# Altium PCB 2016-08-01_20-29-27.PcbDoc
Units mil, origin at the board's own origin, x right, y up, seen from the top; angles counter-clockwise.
Board outline 2000 x 2400 mil, 4 copper layers (Top Layer, MidLayer1, MidLayer2, Bottom Layer); 12 components, 6 nets, 24 pads, 32 vias.
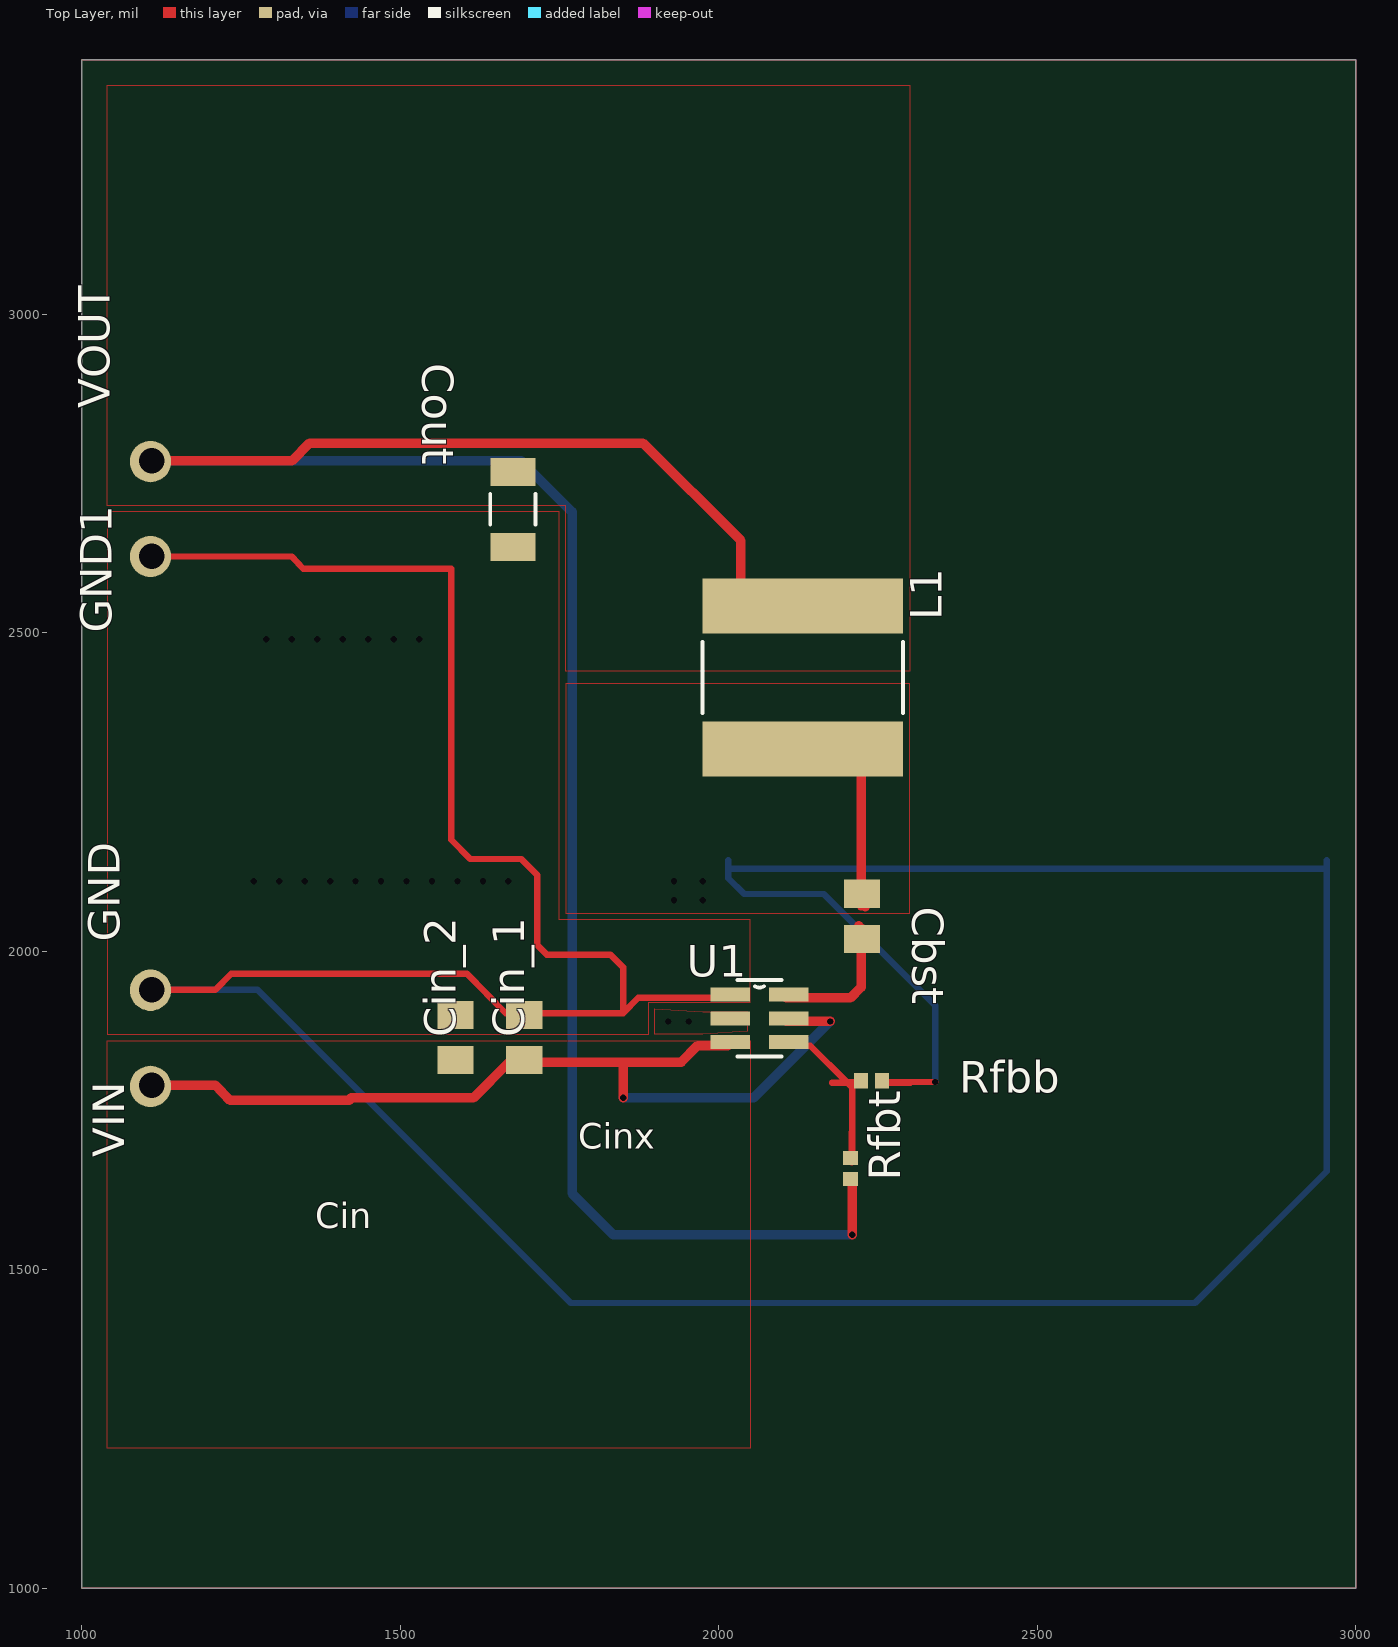
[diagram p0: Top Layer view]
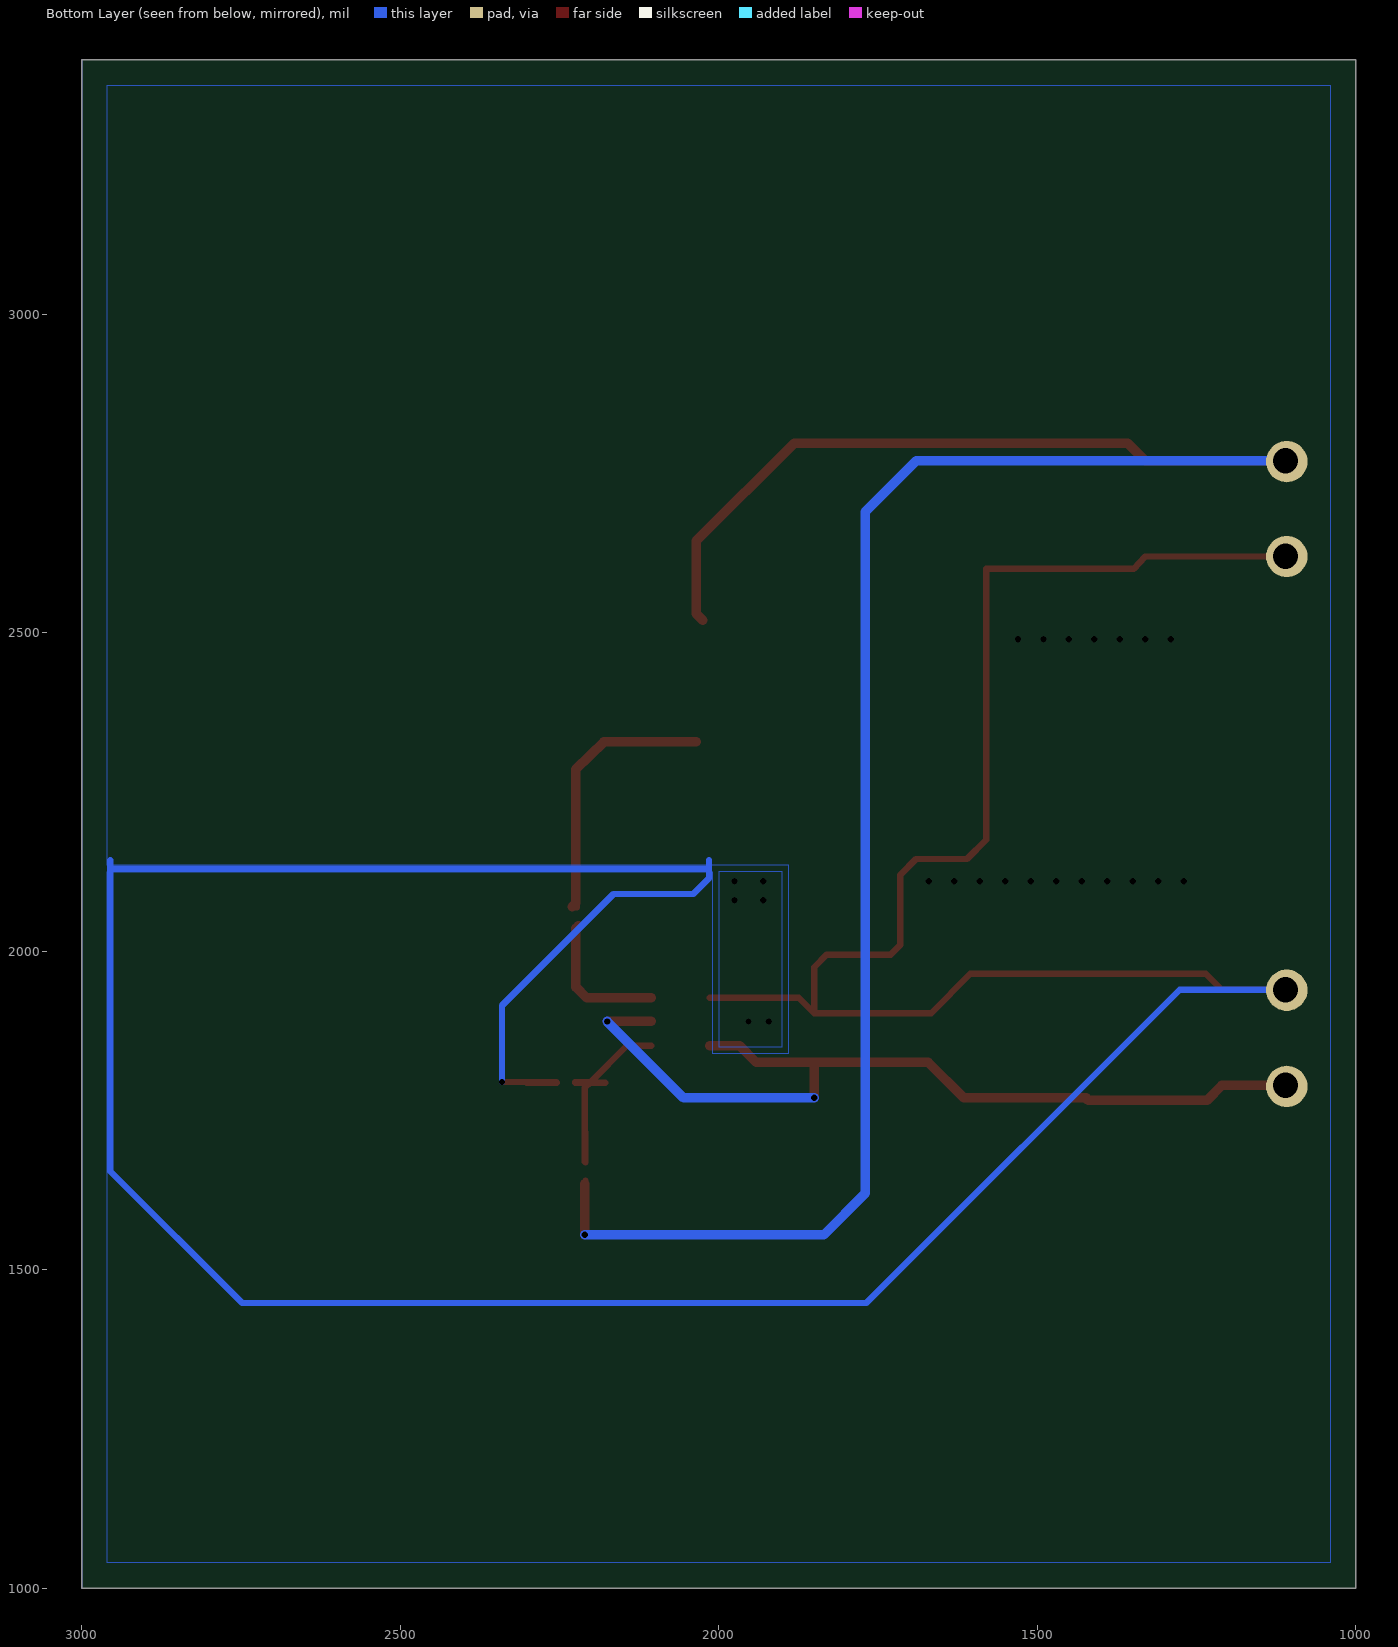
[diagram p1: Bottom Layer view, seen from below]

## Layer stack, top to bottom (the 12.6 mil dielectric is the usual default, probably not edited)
Top Layer: signal copper 1.4
Dielectric: core 12.6, FR-4, Dk 4.8
MidLayer1: signal copper 1.4
Dielectric: prepreg 12.6, FR-4, Dk 4.8
MidLayer2: signal copper 1.4
Dielectric: core 12.6, FR-4, Dk 4.8
Bottom Layer: signal copper 1.4

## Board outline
1000,1000 3000,1000 3000,3400 1000,3400

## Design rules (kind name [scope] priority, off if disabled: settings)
PlaneConnect [All] p0: scope1count=1 scope1_0_kind=Board scope1_0_value=Board scope2count=1 scope2_0_kind=Board scope2_0_value=Board commentlength=0 planeconnectstyle=Direct reliefexpansion=20 reliefentries=4 reliefconductorwidth=10 reliefairgap=10
PlaneConnect [All] p1: planeconnectstyle=Direct reliefexpansion=20 reliefentries=4 reliefconductorwidth=10 reliefairgap=10
PolygonConnect [All] p0: scope1count=1 scope1_0_kind=Board scope1_0_value=Board scope2count=1 scope2_0_kind=Board scope2_0_value=Board commentlength=0 connectstyle=Direct reliefconductorwidth=10 reliefentries=4 polygonreliefangle="90 Angle"
PolygonConnect [All] p1: connectstyle=Direct reliefconductorwidth=10 reliefentries=4 polygonreliefangle="90 Angle"

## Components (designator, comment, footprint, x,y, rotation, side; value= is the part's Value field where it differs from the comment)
Cbst "" 0805 2225,2055 r270 top
Cin_1 "" 0805 1695,1865 r90 top
Cin_2 "" 0805 1587,1865 r90 top
Cout "" 1206 1677,2694 r270 top
GND "" TP-1502 1108,1939 r90 top
GND1 "" TP-1502 1108,2620 r90 top
L1 "" SRN8040 2132,2430 r90 top
Rfbb "" 0402 2240,1797 r0 top
Rfbt "" 0402 2207,1659 r90 top
U1 "" DDC0006A 2064,1895 r0 top
VIN "" TP-1502 1108,1788 r90 top
VOUT "" TP-1502 1108,2769 r90 top

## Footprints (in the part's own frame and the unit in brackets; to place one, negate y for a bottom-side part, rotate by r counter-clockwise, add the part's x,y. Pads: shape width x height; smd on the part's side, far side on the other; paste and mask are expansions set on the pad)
0402 [mil]
  rect 22x24 smd: 1(-16.5,0) 2(16.5,0)
0805 [mil]
  rect 44x57 smd: 1(-35.5,0) 2(35.5,0)
1206 [mil]
  rect 44x71 smd: 1(-59,0) 2(59,0)
  silkscreen extent -24,-36 24,36
DDC0006A [mil]
  rect 62x22 smd: 1(-46,37.4) 2(-46,0) 3(-46,-37.4) 4(46,-37.4) 5(46,0) 6(46,37.4)
  silkscreen extent -34,-60 34,60
SRN8040 [mm]
  rect 2.2x8 smd: 1(-2.85,0) 2(2.85,0)
  silkscreen extent -1.42,-4 1.42,4
TP-1502 [mil]
  round 65 / inner round 0 / far side round 65 hole 32: 1(0,0)

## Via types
v1: diameter 0, hole 10, Top Layer to Bottom Layer, 28 vias
v2: diameter 0, hole 40, Top Layer to Bottom Layer, 4 vias

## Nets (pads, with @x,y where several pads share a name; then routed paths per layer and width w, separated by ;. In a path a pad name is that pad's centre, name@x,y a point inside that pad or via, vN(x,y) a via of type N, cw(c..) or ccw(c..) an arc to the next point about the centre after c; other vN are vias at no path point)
0: Cin_1.2 Cin_2.2 Cout.2 GND1.1 GND.1 Rfbb.2 U1.1 | length 6594.1
  Top Layer w10: v2(1110,1940) 1210,1940 1235,1965 1605,1965 1666,1903 1850,1903 ; v2(1110,2620) 1330,2620 1348,2601 1580,2601 1580,2175 1610,2145 1690,2145 1715,2120 1715,2010 1730,1995 1830,1995 1850,1975 1850,1903 ; U1.1@2014,1927 1874,1927 1850,1903 ; Rfbb.2@2254,1794 2301,1794 ; Rfbb.2@2255,1795 2278,1795 v1(2340,1795)
  Bottom Layer w10: v2(1110,1940) 1276,1940 1768,1448 2748,1448 2955,1655 2955,2130 ; 2015,2143 2015,2130 ; v1(2340,1795) 2340,1915 2165,2090 2040,2090 2015,2115 2015,2130 ; 2955,2143 2955,2130 ; 2015,2130 2955,2130
  other v1: 1270,2110 1310,2110 1350,2110 1390,2110 1430,2110 1470,2110 1510,2110 1550,2110 1590,2110 1630,2110 1670,2110 1290,2490 1330,2490 1370,2490 1410,2490 1450,2490 1490,2490 1530,2490
2: Cin_1.1 Cin_2.1 U1.3 U1.5 VIN.1 | length 1449.9
  Top Layer w15: v2(1110,1790) 1210,1790 1233,1766 1420,1766 1423,1770 1615,1770 1671,1826 1850,1826 ; v1(1850,1770) 1850,1826 ; U1.3@2014,1852 1967,1852 1941,1826 1850,1826 ; U1.5@2106,1890 v1(2175,1890)
  Bottom Layer w15: v1(1850,1770) 2055,1770 v1(2175,1890)
4: Cout.1 L1.2 Rfbt.1 VOUT.1 | length 3485.9
  Top Layer w10: 2209,1593 Rfbt.1@2209,1640
  Top Layer w15: v2(1110,2770) 1330,2770 1358,2798 1580,2798 1881,2798 2035,2645 2035,2530 L1.2@2025,2520 ; v1(2210,1555) 2210,1616 Rfbt.1@2210,1635
  Bottom Layer w15: v2(1110,2770) 1690,2770 1770,2690 1770,1620 1835,1555 v1(2210,1555)
5: Rfbb.1 Rfbt.2 U1.4 | length 365.3
  Top Layer w10: U1.4@2106,1852 2144,1852 2201,1795 ; 2178,1794 Rfbb.1@2225,1794 ; Rfbt.2@2209,1669 2209,1716 ; Rfbt.2@2210,1670 2210,1693 2210,1786 2201,1795 ; Rfbb.1@2225,1795 2201,1795
7: Cbst.1 L1.1 U1.2 | length 486
  Top Layer w10: Cbst.1@2223,2069 2223,2130
  Top Layer w15: L1.1@2035,2329 2180,2329 2224,2286 2224,2095 2224,2076 Cbst.1@2230,2070
  other v1: 1921,1890 1953,1890 1930,2080 1975,2080 1930,2110 1975,2110
10: Cbst.2 U1.6 | length 283.7
  Top Layer w10: 2223,1979 Cbst.2@2223,2040
  Top Layer w15: U1.6@2106,1927 2207,1927 2224,1944 2224,2015 2224,2036 Cbst.2@2220,2040

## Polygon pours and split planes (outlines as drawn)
4 on Top Layer " " (solid, pour order 1): 2300,2440 1760,2440 1760,2700 1040,2700 1040,3360 2300,3360
7 on Top Layer " " (solid, pour order 2): 2300,2420 1760,2420 1760,2060 2300,2060
2 on Top Layer " " (solid, pour order 3): 1040,1860 2050,1860 2050,1220 1040,1220
7 on Top Layer " " (solid, pour order 4): 2045,1875 1975,1870 1900,1870 1900,1910 1975,1905 2045,1905
0 on Top Layer " " (solid, pour order 6): 1040,1870 1890,1870 1890,1920 2050,1920 2050,2050 1750,2050 1750,2690 1040,2690
7 on Bottom Layer " " (solid, pour order 0): 1900,2125 2000,2125 2000,1850 1900,1850
0 on Bottom Layer " " (solid, pour order 5): 1890,2135 2960,2135 2960,3360 1040,3360 1040,1040 2960,1040 2960,2125 2010,2125 2010,1840 1890,1840

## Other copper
Multi-Layer:
  the board outline again, w1

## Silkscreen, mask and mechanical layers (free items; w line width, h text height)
Top Overlay:
  text "Cinx" at 1780,1690 h40
  text "Cin" at 1367,1565 h40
